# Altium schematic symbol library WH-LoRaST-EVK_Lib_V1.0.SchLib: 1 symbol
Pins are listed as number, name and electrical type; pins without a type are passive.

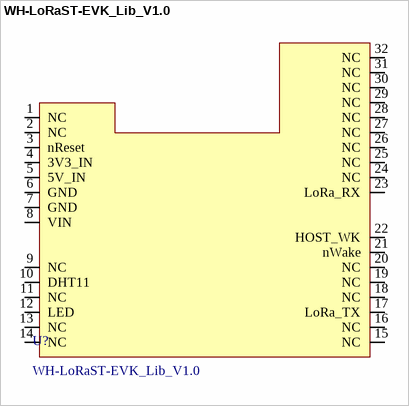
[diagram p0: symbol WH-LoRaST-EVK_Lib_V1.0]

## WH-LoRaST-EVK_Lib_V1.0
designator U?
pins: 1 NC, 2 NC, 3 nReset, 4 3V3_IN, 5 5V_IN, 6 GND, 7 GND, 8 VIN, 9 NC, 10 DHT11, 11 NC, 12 LED, 13 NC, 14 NC, 15 NC, 16 NC, 17 LoRa_TX, 18 NC, 19 NC, 20 NC, 21 nWake, 22 HOST_WK, 23 LoRa_RX, 24 NC, 25 NC, 26 NC, 27 NC, 28 NC, 29 NC, 30 NC, 31 NC, 32 NC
